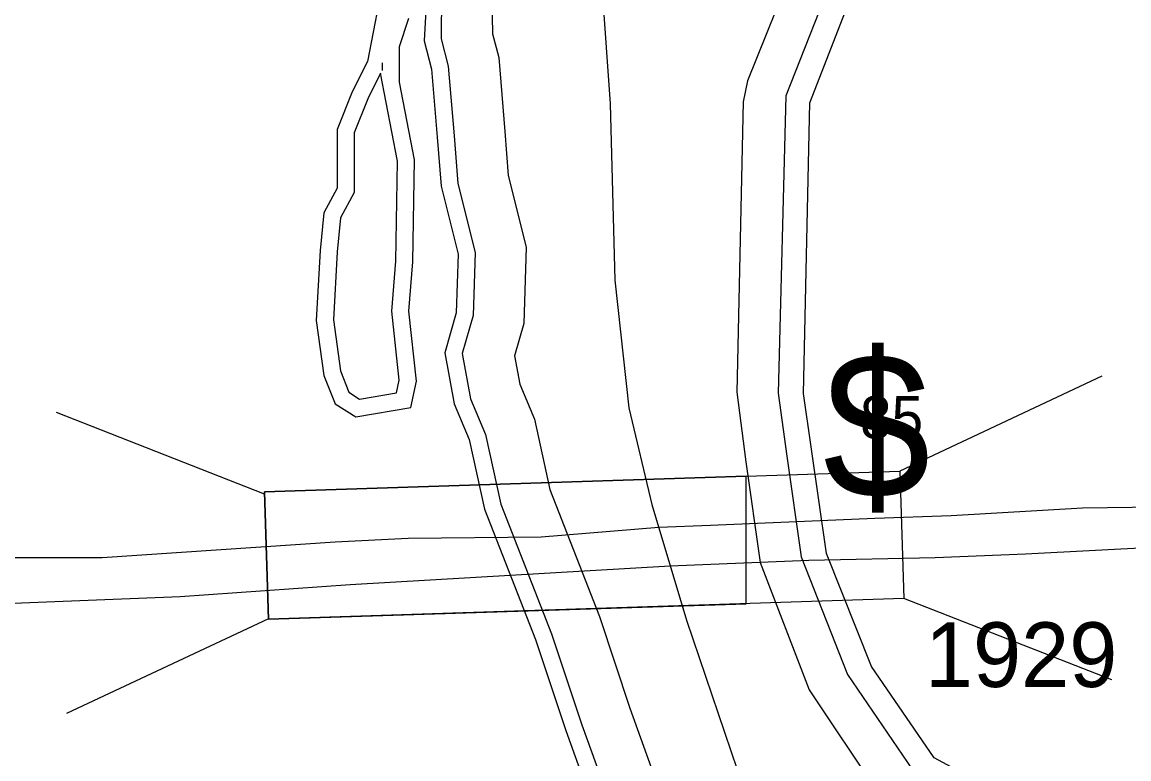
# Model space of a CAD drawing. Extents: x 1364363 to 1407445, y 538563 to 573342.
# Drawn here: x 1397619 to 1399758, y 554435 to 555859 of the extents above; entities that cross this region are included whole.
import ezdxf

# ---------------------------------------------------------------- set-up
doc = ezdxf.new("R2010")
doc.units = 0
for name, color, linetype in [('Default', 7, 'Continuous'), ('Exist Boundary Political CountyLine', 7, 'Continuous'), ('Exist Hydrographic Bay Label', 7, 'Continuous'), ('Exist Hydrographic Buffer Line', 7, 'Continuous'), ('Exist Hydrographic Creek Double Shore', 7, 'Continuous'), ('Exist Road Primary Interstate Divided Center Attributed', 7, 'Continuous'), ('Exist Road Primary Interstate Shield CELL', 7, 'Continuous'), ('Exist Road Primary Interstate Structure Standard Bridge CELL', 7, 'Continuous'), ('Exist Road Secondary Type 51 Number Label', 7, 'Continuous')]:
    doc.layers.add(name, color=color, linetype=linetype)

msp = doc.modelspace()

# ---------------------------------------------------------------- linework, layer by layer
at = {"layer": 'Exist Boundary Political CountyLine'}
msp.add_lwpolyline([(1399018.9, 560380.4), (1398953.9, 560208.6), (1398640.8, 559221.5), (1398586.6, 558809.5), (1398586.5, 558515.3), (1398600.3, 558218.9), (1398661.9, 557709.2), (1398674.4, 557256.8), (1398690.2, 556762.2), (1398715.8, 556263.5), (1398756.1, 555700.4), (1398765.1, 555360), (1398791.9, 555113.4), (1398836.2, 554926.4), (1398903.5, 554702.9), (1399001.5, 554414.6), (1399018.9, 554371.9)], dxfattribs=at)
at = {"layer": 'Exist Hydrographic Bay Label'}
msp.add_lwpolyline([(1399892.8, 553333.8), (1399464.7, 554392.8), (1399381.8, 554437.1), (1399260.7, 554613.5), (1399173.7, 554831.9), (1399129.7, 555141.3), (1399141.7, 555702.4), (1399237.7, 555949.9)], dxfattribs=at)
at = {"layer": 'Exist Hydrographic Buffer Line'}
for points in [[(1399132.1, 556020.5), (1399020.9, 555745.2), (1399012.8, 555704.4), (1399000.9, 555143.3), (1399018.3, 555008.7), (1399046, 554814.4), (1399140.3, 554568.6), (1399273.9, 554368.6), (1399312.8, 554332.6), (1399360.8, 554306.9), (1399772.6, 553288.3)], [(1398430.5, 555998.6), (1398429.1, 555826), (1398443, 555773.5), (1398454.3, 555639), (1398461.4, 555546.7), (1398494.7, 555413.4), (1398490.7, 555291.5), (1398469.8, 555218.3), (1398486, 555130.7), (1398515, 555061.8), (1398544.4, 554927), (1398642.4, 554676.5), (1398700.9, 554500.8), (1398756.3, 554347.3), (1398714.8, 554245.8), (1398628, 554189.2)], [(1398430.5, 555998.6), (1398429.1, 555826), (1398443, 555773.5), (1398454.3, 555639), (1398461.4, 555546.7), (1398494.7, 555413.4), (1398490.7, 555291.5), (1398469.8, 555218.3), (1398486, 555130.7), (1398515, 555061.8), (1398544.4, 554927), (1398642.4, 554676.5), (1398700.9, 554500.8), (1398756.3, 554347.3), (1398714.8, 554245.8), (1398628, 554189.2)], [(1398526, 555974.7), (1398528.3, 555835.9), (1398540.4, 555790.4), (1398552.4, 555646.9), (1398558.9, 555562.5), (1398593.5, 555423.9), (1398588.7, 555276.2), (1398570.8, 555213.5), (1398580.9, 555159.1), (1398609.3, 555091.6), (1398638.9, 554955.6), (1398735, 554710), (1398793.9, 554533), (1398861.7, 554345.1), (1398807.5, 554177.3), (1398873, 554055.9)], [(1398526, 555974.7), (1398528.3, 555835.9), (1398540.4, 555790.4), (1398552.4, 555646.9), (1398558.9, 555562.5), (1398593.5, 555423.9), (1398588.7, 555276.2), (1398570.8, 555213.5), (1398580.9, 555159.1), (1398609.3, 555091.6), (1398638.9, 554955.6), (1398735, 554710), (1398793.9, 554533), (1398861.7, 554345.1), (1398807.5, 554177.3), (1398873, 554055.9)], [(1399196.6, 555973.1), (1399095.5, 555716.3), (1399080.8, 555141.7), (1399097.5, 555020), (1399125.2, 554825.7), (1399214.6, 554598.2), (1399339.8, 554413.9), (1399424.1, 554363.8), (1399846.7, 553318.3), (1400104.9, 553106.6), (1400143.4, 553100.4), (1400198.9, 553147), (1400280.1, 553367.5), (1400335.7, 553455.2), (1400431.8, 553469.7), (1400464.1, 553437.4), (1400469.2, 553375.2), (1400375.1, 553112.9), (1400376.8, 552898.2), (1400396.7, 552864.4), (1400555, 552773.1), (1400617.3, 552693.6), (1400742.5, 552014.6)], [(1398315.7, 555765.2), (1398315.7, 555779.8)], [(1398315.7, 555765.2), (1398315.7, 555779.8)], [(1398311.7, 555759.7), (1398287.2, 555710.6), (1398260.8, 555644.7), (1398260.8, 555529.5), (1398234.5, 555480.5), (1398227.9, 555414.7), (1398220.8, 555283.4), (1398234.4, 555184.5), (1398250.9, 555143.3), (1398271.5, 555130.2), (1398343, 555142.5), (1398348.2, 555166.8), (1398333.8, 555299.8), (1398341.3, 555396.8), (1398344.9, 555589.7), (1398311.7, 555759.7)], [(1398311.7, 555759.7), (1398287.2, 555710.6), (1398260.8, 555644.7), (1398260.8, 555529.5), (1398234.5, 555480.5), (1398227.9, 555414.7), (1398220.8, 555283.4), (1398234.4, 555184.5), (1398250.9, 555143.3), (1398271.5, 555130.2), (1398343, 555142.5), (1398348.2, 555166.8), (1398333.8, 555299.8), (1398341.3, 555396.8), (1398344.9, 555589.7), (1398311.7, 555759.7)]]:
    msp.add_lwpolyline(points, dxfattribs=at)
at = {"layer": 'Exist Hydrographic Creek Double Shore'}
for points in [[(1398308.4, 555895.8), (1398286.5, 555782.5), (1398257.2, 555724.1), (1398228, 555651), (1398228, 555537.7), (1398202.5, 555490.3), (1398195.2, 555417.2), (1398187.9, 555282), (1398202.5, 555176.1), (1398224.4, 555121.3), (1398264.5, 555095.7), (1398370.4, 555114), (1398381.4, 555165.1), (1398366.8, 555300.3), (1398374.1, 555395.3), (1398377.7, 555592.5), (1398348.5, 555742.3), (1398348.5, 555811.7), (1398366.8, 555866.5)], [(1398308.4, 555895.8), (1398286.5, 555782.5), (1398257.2, 555724.1), (1398228, 555651), (1398228, 555537.7), (1398202.5, 555490.3), (1398195.2, 555417.2), (1398187.9, 555282), (1398202.5, 555176.1), (1398224.4, 555121.3), (1398264.5, 555095.7), (1398370.4, 555114), (1398381.4, 555165.1), (1398366.8, 555300.3), (1398374.1, 555395.3), (1398377.7, 555592.5), (1398348.5, 555742.3), (1398348.5, 555811.7), (1398366.8, 555866.5)], [(1398399.6, 555881.2), (1398396, 555822.7), (1398410.6, 555767.9), (1398421.6, 555636.4), (1398428.9, 555541.4), (1398461.7, 555409.9), (1398458.1, 555296.6), (1398436.2, 555219.9), (1398454.4, 555121.3), (1398483.6, 555051.9), (1398512.9, 554917.5), (1398611.5, 554665.4), (1398669.9, 554490), (1398721.2, 554348.1), (1398688.3, 554267.7), (1398604.3, 554212.9), (1398538.6, 554231.2), (1398465.6, 554311.5), (1398359, 554401.1)], [(1398399.6, 555881.2), (1398396, 555822.7), (1398410.6, 555767.9), (1398421.6, 555636.4), (1398428.9, 555541.4), (1398461.7, 555409.9), (1398458.1, 555296.6), (1398436.2, 555219.9), (1398454.4, 555121.3), (1398483.6, 555051.9), (1398512.9, 554917.5), (1398611.5, 554665.4), (1398669.9, 554490), (1398721.2, 554348.1), (1398688.3, 554267.7), (1398604.3, 554212.9), (1398538.6, 554231.2), (1398465.6, 554311.5), (1398359, 554401.1)]]:
    msp.add_lwpolyline(points, dxfattribs=at)
at = {"layer": 'Exist Road Primary Interstate Divided Center Attributed'}
for points in [[(1402889.9, 554881.6), (1402809.6, 554889.8), (1402781.4, 554892.7), (1402628.7, 554906.1), (1402436.1, 554924.4), (1402264.4, 554938.2), (1402075, 554951.4), (1402066.2, 554951.9), (1401820.9, 554959.8), (1401703.2, 554961.2), (1401454.2, 554964.3), (1401140.9, 554963), (1400812.9, 554956.8), (1400615.7, 554948.8), (1400380.2, 554939.8), (1400229.5, 554933.3), (1400151.5, 554930.7), (1400046.8, 554927.3), (1399813.2, 554921.2), (1399668.9, 554919.2), (1399415.1, 554904.8), (1399267.1, 554899.4), (1398949.5, 554886), (1398849.6, 554881.8)], [(1398871.8, 554808), (1399139.7, 554819.3), (1399383.9, 554824.3), (1399558.4, 554831.4), (1399816.6, 554844.8), (1399967.8, 554848.3), (1400081.5, 554856), (1400107.8, 554857.8), (1400231.2, 554866.9), (1400703.7, 554883.3), (1401109.6, 554891.3), (1401566.5, 554885.6), (1401573.3, 554885.6), (1401953.8, 554874.5), (1402075, 554867.8), (1402227.7, 554859.3), (1402444.7, 554849.5), (1402685, 554837.7), (1402785.5, 554830.5), (1402799.6, 554829.3), (1402883.2, 554821.9)], [(1398849.6, 554881.8), (1398622.7, 554863.5), (1398365.7, 554860.9), (1398224.1, 554853.5), (1397774.1, 554823.3), (1397511, 554823.3), (1397410.2, 554820.3), (1397285.4, 554822.5), (1397027.4, 554812.3), (1396859.2, 554806.8), (1396750.2, 554795.2)], [(1398849.6, 554881.8), (1398622.7, 554863.5), (1398365.7, 554860.9), (1398224.1, 554853.5), (1397774.1, 554823.3), (1397511, 554823.3), (1397410.2, 554820.3), (1397285.4, 554822.5), (1397027.4, 554812.3), (1396859.2, 554806.8), (1396750.2, 554795.2)], [(1396472.2, 554699.3), (1396679.9, 554705.3), (1396910.8, 554708.3), (1397203.9, 554721.7), (1397257.8, 554724.7), (1397504, 554732.2), (1397924.9, 554748.6), (1398253, 554772.1), (1398871.8, 554808)], [(1396472.2, 554699.3), (1396679.9, 554705.3), (1396910.8, 554708.3), (1397203.9, 554721.7), (1397257.8, 554724.7), (1397504, 554732.2), (1397924.9, 554748.6), (1398253, 554772.1), (1398871.8, 554808)]]:
    msp.add_lwpolyline(points, dxfattribs=at)
at = {"layer": 'Exist Road Primary Interstate Structure Standard Bridge CELL'}
for p, q in [((1399706.2, 555174.4), (1399315.4, 554991.2)), ((1398087.8, 554946.7), (1397685.9, 555104)), ((1398087.8, 554946.7), (1397685.9, 555104)), ((1399018.9, 554734.9), (1399018.9, 554981.5)), ((1399725.3, 554587.6), (1399323.4, 554744.9)), ((1398095.7, 554705.9), (1397704.8, 554522.7)), ((1398095.7, 554705.9), (1397704.8, 554522.7))]:
    msp.add_line(p, q, dxfattribs=at)
msp.add_lwpolyline([(1399323.4, 554744.9), (1398095.7, 554704.8), (1398087.6, 554951.1), (1399315.4, 554991.2)], close=True, dxfattribs=at)
msp.add_lwpolyline([(1399018.9, 554981.5), (1398087.6, 554951.1), (1398095.7, 554704.8), (1399018.9, 554734.9)], dxfattribs=at)

# ---------------------------------------------------------------- texts
at = {"layer": 'Default'}
msp.add_text('$', height=278.9, dxfattribs=at).set_placement((1399167.2, 554939.2))
at = {"layer": 'Exist Road Primary Interstate Shield CELL'}
msp.add_text('85', height=82.02, dxfattribs=at).set_placement((1399238.7, 555054))
at = {"layer": 'Exist Road Secondary Type 51 Number Label'}
msp.add_text('1929', height=125, dxfattribs=at).set_placement((1399364.1, 554573.9))

doc.saveas('drawing.dxf')
